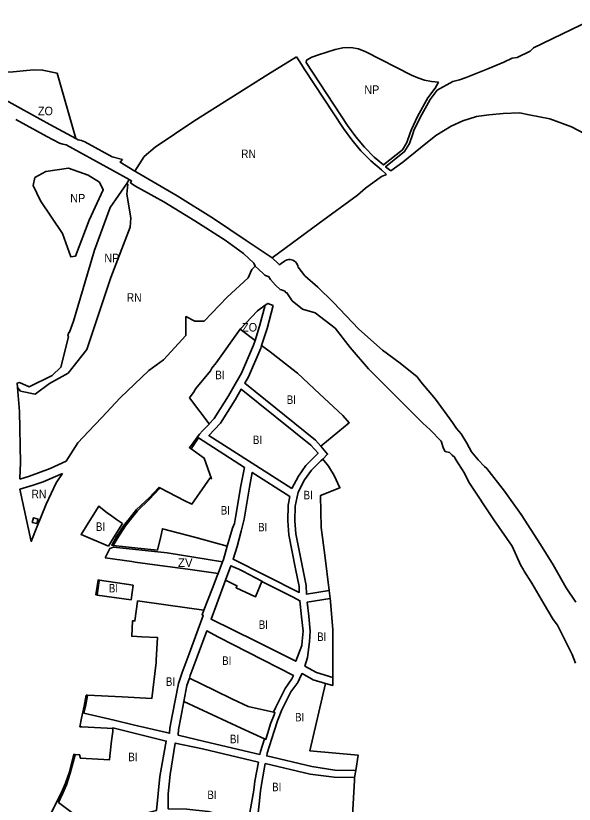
# Model space of a CAD drawing. Extents: x -650971 to -642489, y -1074311 to -1062745.
# Drawn here: x -645941 to -645155, y -1069933 to -1068825 of the extents above; entities that cross this region are included whole.
import ezdxf

# ---------------------------------------------------------------- set-up
doc = ezdxf.new("R2010")
doc.units = 0
doc.header["$LTSCALE"] = 4.8
for name, color, linetype, lineweight in [('15', 7, 'Continuous', 35), ('2', 7, 'Continuous', 35), ('24', 7, 'Continuous', 35), ('40', 7, 'Continuous', 35), ('42', 7, 'Continuous', 35), ('48', 7, 'Continuous', 35), ('62', 7, 'Continuous', 35), ('7', 7, 'Continuous', 35)]:
    doc.layers.add(name, color=color, linetype=linetype, lineweight=lineweight)

msp = doc.modelspace()

# ---------------------------------------------------------------- linework, layer by layer
at = {"layer": '15'}
for points in [[(-645604.114, -1069281.49), (-645597.738, -1069261.522), (-645589.844, -1069231.908), (-645586.39, -1069229.32), (-645578.713, -1069232.375)], [(-645578.713, -1069232.375), (-645587.298, -1069264.578), (-645594.94, -1069288.511)], [(-645668.722, -1069398.75), (-645661.477, -1069390.91), (-645641.511, -1069359.099), (-645635.995, -1069349.527), (-645623.307, -1069327.508), (-645606.256, -1069288.199), (-645604.114, -1069281.49)], [(-645594.94, -1069288.511), (-645596.062, -1069292.027), (-645613.576, -1069332.402), (-645618.766, -1069341.409), (-645519.097, -1069421.579), (-645511.464, -1069429.794)], [(-645678.06, -1069408.54), (-645668.61, -1069398.9), (-645668.722, -1069398.75)], [(-645694.21, -1069433.78), (-645696.45, -1069432.21), (-645682.28, -1069412.88), (-645678.06, -1069408.54)], [(-645643.16, -1069570.6), (-645636.09, -1069545.31), (-645633.29, -1069538.7), (-645631.62, -1069530.161), (-645624.041, -1069485.561), (-645619.119, -1069459.68), (-645683.883, -1069418.357), (-645694.21, -1069433.78)], [(-645511.464, -1069429.794), (-645502.142, -1069441.313), (-645508.994, -1069447.955)], [(-645508.994, -1069447.955), (-645511.585, -1069450.466), (-645524.812, -1069463.425), (-645534.584, -1069477.365), (-645543.548, -1069494.404), (-645547.654, -1069514.049), (-645548.207, -1069534.609), (-645546.74, -1069552.954), (-645537.354, -1069600.095), (-645532.36, -1069625.648), (-645531.753, -1069637.96), (-645500.137, -1069632.833), (-645498.61, -1069643.729)], [(-645803.513, -1069569.263), (-645805.66, -1069569.03), (-645798.53, -1069556.3), (-645787.64, -1069539.88), (-645780.85, -1069531.55), (-645770.66, -1069519.07), (-645753.05, -1069502.47), (-645739.3, -1069487.81), (-645737.897, -1069488.534)], [(-645737.897, -1069488.534), (-645738.986, -1069489.868), (-645752.715, -1069504.328), (-645769.369, -1069520.672), (-645779.376, -1069532.962), (-645786.388, -1069541.673), (-645798.102, -1069559.972), (-645803.513, -1069569.263)], [(-645648.68, -1069589.06), (-645644.56, -1069575.61), (-645643.16, -1069570.6)], [(-645664.19, -1069629.24), (-645657.52, -1069612.2), (-645656.15, -1069608.71), (-645649.91, -1069592.39), (-645648.68, -1069589.06)], [(-645594.818, -1069620.139), (-645594.58, -1069619.56), (-645621.56, -1069605.68), (-645626.95, -1069602.91), (-645638.203, -1069597.8), (-645645.715, -1069618.085)], [(-645827.94, -1069638.8), (-645824.95, -1069618.01), (-645823.082, -1069618.279)], [(-645823.082, -1069618.279), (-645823.13, -1069618.452), (-645825.295, -1069632.053), (-645826.133, -1069638.843), (-645826.15, -1069639.045), (-645827.94, -1069638.8)], [(-645645.715, -1069618.085), (-645658.119, -1069651.601), (-645665.961, -1069673.028), (-645602.91, -1069703.88), (-645546.93, -1069731.98), (-645538.579, -1069710.102), (-645537.8, -1069703.696), (-645536.707, -1069689.842), (-645538.744, -1069669.644), (-645541.064, -1069647.092), (-645550.62, -1069642.176), (-645594.818, -1069620.139)], [(-645839.658, -1069779.835), (-645839.721, -1069780.247), (-645842.728, -1069795.578), (-645844.737, -1069804.875), (-645802.431, -1069814.987), (-645775.326, -1069821.576), (-645724.25, -1069833.353), (-645723.777, -1069826.243), (-645720.632, -1069808.792), (-645711.852, -1069763.14), (-645706.663, -1069747.998), (-645696.794, -1069721.756), (-645676.984, -1069667.634), (-645678.73, -1069666.78), (-645676.34, -1069660.28), (-645670.23, -1069644.67), (-645664.19, -1069629.24)], [(-645498.61, -1069643.729), (-645530.797, -1069648.949), (-645528.772, -1069668.628), (-645526.643, -1069689.732), (-645527.824, -1069704.697), (-645530.534, -1069726.969), (-645533.953, -1069739.166), (-645518, -1069748), (-645495, -1069754.815)], [(-645578.134, -1069803.731), (-645575.153, -1069796.472), (-645561.956, -1069770.224), (-645552.437, -1069756.749), (-645550.184, -1069752.242), (-645614.28, -1069719.27), (-645655.45, -1069698.05), (-645671.999, -1069689.523), (-645685.351, -1069726.002), (-645695.176, -1069752.125), (-645696.517, -1069756.039)], [(-645696.517, -1069756.039), (-645700.028, -1069766.286), (-645704.355, -1069788.786)], [(-645504.976, -1069763.332), (-645522.277, -1069758.205), (-645538.096, -1069749.446), (-645539.126, -1069751.764), (-645544.108, -1069761.733), (-645553.635, -1069775.217), (-645566.341, -1069800.49), (-645572.56, -1069815.628), (-645577.497, -1069830.237), (-645587.052, -1069861.272), (-645587.785, -1069865.117), (-645524.43, -1069879.921), (-645492, -1069885), (-645462.303, -1069885.376), (-645464.288, -1069895.362)], [(-645495, -1069754.815), (-645495, -1069766), (-645504.976, -1069763.332)], [(-645850.63, -1069824.09), (-645848.35, -1069812.09), (-645844.57, -1069795.07), (-645841.41, -1069779.76), (-645839.658, -1069779.835)], [(-645704.355, -1069788.786), (-645708.633, -1069811.027), (-645711.644, -1069827.736), (-645712.203, -1069836.131), (-645675.369, -1069844.625), (-645597.216, -1069862.91), (-645596.458, -1069858.935), (-645590.964, -1069841.09)], [(-645590.964, -1069841.09), (-645589.23, -1069841.89), (-645582.31, -1069820.05), (-645577.52, -1069807.26), (-645576.34, -1069804.13), (-645578.134, -1069803.731)], [(-645857.204, -1069862.954), (-645857.289, -1069863.338), (-645863.95, -1069889.468), (-645869.262, -1069905.935), (-645874.219, -1069917.496), (-645880.431, -1069930.3), (-645833, -1069966), (-645806, -1069959), (-645768.424, -1069948.431), (-645742.967, -1069941.862), (-645738.039, -1069894.231), (-645729.006, -1069844.136), (-645777.852, -1069832.241), (-645804.185, -1069825.84), (-645804.28, -1069826.76)], [(-645804.28, -1069826.76), (-645812.18, -1069826.3), (-645847.62, -1069824.26), (-645850.63, -1069824.09)], [(-645894.25, -1069958.7), (-645895.66, -1069958.42), (-645892.09, -1069947.98), (-645876.15, -1069916.47), (-645870.89, -1069903.5), (-645865.78, -1069888.76), (-645858.78, -1069862.84), (-645857.204, -1069862.954)], [(-645464.288, -1069895.362), (-645492.842, -1069895), (-645526.451, -1069890.745), (-645589.84, -1069875.892), (-645594.866, -1069902.242), (-645596.463, -1069914.335), (-645598.491, -1069932.472), (-645601.753, -1069962.317), (-645547.4, -1069976.382), (-645490.814, -1069988.074), (-645469.701, -1069990.011)]]:
    msp.add_lwpolyline(points, dxfattribs=at)
for points in [[(-645552.336, -1069489.579), (-645543.158, -1069472.134), (-645532.534, -1069456.978), (-645515.509, -1069439.769), (-645525.761, -1069428.736), (-645623.694, -1069349.962), (-645632.191, -1069364.707), (-645652.804, -1069397.548), (-645669.039, -1069415.116)], [(-645555.072, -1069500.545), (-645608.04, -1069466.749), (-645612.028, -1069487.724), (-645619.662, -1069532.642), (-645623.814, -1069549.548), (-645629.102, -1069570.857), (-645635.153, -1069588.78), (-645541.922, -1069635.264), (-645542.336, -1069626.862), (-645547.188, -1069602.035), (-645556.685, -1069554.337), (-645558.241, -1069534.874), (-645557.65, -1069512.879)], [(-645599.271, -1069873.685), (-645677.849, -1069855.3), (-645716.277, -1069847.01), (-645723.668, -1069891.356), (-645726.131, -1069918.457), (-645726.542, -1069939.398), (-645699.889, -1069939.714), (-645670.325, -1069943.002), (-645625.979, -1069954.92), (-645614.072, -1069957.797), (-645606.07, -1069913.163), (-645604.424, -1069900.701)]]:
    msp.add_lwpolyline(points, close=True, dxfattribs=at)
at = {"layer": '2'}
for points in [[(-645696.19, -1069362.01), (-645692.38, -1069356.67), (-645690.81, -1069354.28), (-645687.22, -1069349), (-645667, -1069324.06), (-645664.89, -1069320.2), (-645658.9, -1069312.83), (-645625.11, -1069265.42), (-645604.114, -1069281.49)], [(-645604.114, -1069281.49), (-645606.256, -1069288.199), (-645623.307, -1069327.508), (-645635.995, -1069349.527), (-645641.511, -1069359.099), (-645661.477, -1069390.91), (-645668.722, -1069398.75), (-645696.19, -1069362.01)], [(-645511.464, -1069429.794), (-645519.097, -1069421.579), (-645618.766, -1069341.409), (-645613.576, -1069332.402), (-645596.062, -1069292.027), (-645594.94, -1069288.511)], [(-645594.94, -1069288.511), (-645583.13, -1069297.55), (-645546.19, -1069325.81), (-645544.26, -1069327.35), (-645513.41, -1069356.18), (-645480.72, -1069386.96), (-645471.738, -1069397.026), (-645511.464, -1069429.794)], [(-645694.21, -1069433.78), (-645683.883, -1069418.357), (-645619.119, -1069459.68), (-645624.041, -1069485.561), (-645631.62, -1069530.161), (-645633.29, -1069538.7), (-645636.09, -1069545.31), (-645643.16, -1069570.6)], [(-645737.897, -1069488.534), (-645702.82, -1069506.64), (-645692.87, -1069511.229), (-645667.31, -1069474.6), (-645665.58, -1069475.61), (-645675.91, -1069446.56), (-645694.21, -1069433.78)], [(-645500.137, -1069632.833), (-645531.753, -1069637.96), (-645532.36, -1069625.648), (-645537.354, -1069600.095), (-645546.74, -1069552.954), (-645548.207, -1069534.609), (-645547.654, -1069514.049), (-645543.548, -1069494.404), (-645534.584, -1069477.365), (-645524.812, -1069463.425), (-645511.585, -1069450.466), (-645508.994, -1069447.955)], [(-645508.994, -1069447.955), (-645501, -1069458), (-645493, -1069471), (-645484.783, -1069488.256), (-645512, -1069499), (-645511, -1069544), (-645506, -1069583), (-645500.137, -1069632.833)], [(-645803.513, -1069569.263), (-645798.102, -1069559.972), (-645786.388, -1069541.673), (-645779.376, -1069532.962), (-645769.369, -1069520.672), (-645752.715, -1069504.328), (-645738.986, -1069489.868), (-645737.897, -1069488.534)], [(-645810.08, -1069570.39), (-645848.78, -1069553.91), (-645836.44, -1069534.5), (-645824.05, -1069514.34), (-645811.75, -1069523.81)], [(-645811.75, -1069523.81), (-645808.1, -1069526.61), (-645799.07, -1069532.8), (-645790.62, -1069538.59)], [(-645790.62, -1069538.59), (-645803.07, -1069558.62), (-645810.08, -1069570.39)], [(-645643.16, -1069570.6), (-645687.29, -1069558.04), (-645734.5, -1069545.89), (-645736.8, -1069556.91), (-645741.14, -1069576.19)], [(-645741.14, -1069576.19), (-645769.04, -1069573), (-645803.513, -1069569.263)], [(-645826.15, -1069639.045), (-645826.133, -1069638.843), (-645825.295, -1069632.053), (-645823.13, -1069618.452), (-645823.082, -1069618.279), (-645775.46, -1069625.13)], [(-645594.818, -1069620.139), (-645550.62, -1069642.176), (-645541.064, -1069647.092), (-645538.744, -1069669.644), (-645536.707, -1069689.842), (-645537.8, -1069703.696), (-645538.579, -1069710.102), (-645546.93, -1069731.98), (-645602.91, -1069703.88), (-645665.961, -1069673.028), (-645658.119, -1069651.601), (-645645.715, -1069618.085)], [(-645645.715, -1069618.085), (-645629.78, -1069626.03), (-645630.93, -1069628.84), (-645603.7, -1069641.75), (-645594.818, -1069620.139)], [(-645775.46, -1069625.13), (-645778.45, -1069645.92), (-645826.151, -1069639.057), (-645826.15, -1069639.045)], [(-645495, -1069754.815), (-645518, -1069748), (-645533.953, -1069739.166), (-645530.534, -1069726.969), (-645527.824, -1069704.697), (-645526.643, -1069689.732), (-645528.772, -1069668.628), (-645530.797, -1069648.949), (-645498.61, -1069643.729)], [(-645498.61, -1069643.729), (-645498, -1069648), (-645495, -1069688), (-645495, -1069754.815)], [(-645839.658, -1069779.835), (-645791.2, -1069781.92), (-645749.48, -1069784.61), (-645743.36, -1069733.7), (-645743.01, -1069730.72), (-645741.43, -1069698.68), (-645763.24, -1069697.58), (-645777.62, -1069696.85), (-645776.45, -1069675.26), (-645773.02, -1069675.47), (-645769.36, -1069648), (-645769.264, -1069647.213), (-645726.57, -1069653.22), (-645676.34, -1069660.28)], [(-645676.34, -1069660.28), (-645678.73, -1069666.78), (-645676.984, -1069667.634), (-645696.794, -1069721.756), (-645706.663, -1069747.998), (-645711.852, -1069763.14), (-645720.632, -1069808.792), (-645723.777, -1069826.243), (-645724.25, -1069833.353), (-645775.326, -1069821.576), (-645802.431, -1069814.987), (-645844.737, -1069804.875), (-645842.728, -1069795.578), (-645839.721, -1069780.247), (-645839.658, -1069779.835)], [(-645696.517, -1069756.039), (-645695.176, -1069752.125), (-645685.351, -1069726.002), (-645671.999, -1069689.523), (-645655.45, -1069698.05), (-645614.28, -1069719.27), (-645550.184, -1069752.242), (-645552.437, -1069756.749), (-645561.956, -1069770.224), (-645575.153, -1069796.472), (-645578.134, -1069803.731)], [(-645578.134, -1069803.731), (-645613.84, -1069795.78), (-645635.79, -1069785.23), (-645660.57, -1069773.31), (-645696.517, -1069756.039)], [(-645462.303, -1069885.376), (-645492, -1069885), (-645524.43, -1069879.921), (-645587.785, -1069865.117), (-645587.052, -1069861.272), (-645577.497, -1069830.237), (-645572.56, -1069815.628), (-645566.341, -1069800.49), (-645553.635, -1069775.217), (-645544.108, -1069761.733), (-645539.126, -1069751.764), (-645538.096, -1069749.446), (-645522.277, -1069758.205), (-645504.976, -1069763.332)], [(-645504.976, -1069763.332), (-645527, -1069858), (-645459.312, -1069864.01), (-645462.303, -1069885.376)], [(-645590.964, -1069841.09), (-645596.458, -1069858.935), (-645597.216, -1069862.91), (-645675.369, -1069844.625), (-645712.203, -1069836.131), (-645711.644, -1069827.736), (-645708.633, -1069811.027), (-645704.355, -1069788.786)], [(-645704.355, -1069788.786), (-645623.75, -1069825.97), (-645590.964, -1069841.09)], [(-645804.28, -1069826.76), (-645804.185, -1069825.84), (-645777.852, -1069832.241), (-645729.006, -1069844.136), (-645738.039, -1069894.231), (-645742.967, -1069941.862), (-645768.424, -1069948.431), (-645806, -1069959), (-645833, -1069966), (-645880.431, -1069930.3), (-645874.219, -1069917.496), (-645869.262, -1069905.935), (-645863.95, -1069889.468), (-645857.289, -1069863.338), (-645857.204, -1069862.954)], [(-645857.204, -1069862.954), (-645850.92, -1069863.41), (-645849.79, -1069868.4), (-645808.84, -1069870.75), (-645808.28, -1069865.39), (-645806.07, -1069844.09), (-645804.38, -1069830.61), (-645804.28, -1069826.76)], [(-645469.701, -1069990.011), (-645490.814, -1069988.074), (-645547.4, -1069976.382), (-645601.753, -1069962.317), (-645598.491, -1069932.472), (-645596.463, -1069914.335), (-645594.866, -1069902.242), (-645589.84, -1069875.892), (-645526.451, -1069890.745), (-645492.842, -1069895), (-645464.288, -1069895.362)], [(-645464.288, -1069895.362), (-645464.206, -1069899.449), (-645469.701, -1069990.011)]]:
    msp.add_lwpolyline(points, dxfattribs=at)
for points in [[(-645552.336, -1069489.579), (-645669.039, -1069415.116), (-645652.804, -1069397.548), (-645632.191, -1069364.707), (-645623.694, -1069349.962), (-645525.761, -1069428.736), (-645515.509, -1069439.769), (-645532.534, -1069456.978), (-645543.158, -1069472.134)], [(-645555.072, -1069500.545), (-645557.65, -1069512.879), (-645558.241, -1069534.874), (-645556.685, -1069554.337), (-645547.188, -1069602.035), (-645542.336, -1069626.862), (-645541.922, -1069635.264), (-645635.153, -1069588.78), (-645629.102, -1069570.857), (-645623.814, -1069549.548), (-645619.662, -1069532.642), (-645612.028, -1069487.724), (-645608.04, -1069466.749)], [(-645599.271, -1069873.685), (-645604.424, -1069900.701), (-645606.07, -1069913.163), (-645614.072, -1069957.797), (-645625.979, -1069954.92), (-645670.325, -1069943.002), (-645699.889, -1069939.714), (-645726.542, -1069939.398), (-645726.131, -1069918.457), (-645723.668, -1069891.356), (-645716.277, -1069847.01), (-645677.849, -1069855.3)]]:
    msp.add_lwpolyline(points, close=True, dxfattribs=at)
at = {"layer": '24'}
for points in [[(-646017.55, -1068909.75), (-645975.31, -1068932.8), (-645933.28, -1068955.74), (-645892.77, -1068977.86), (-645856.26, -1068997.79)], [(-645850.79, -1069016.84), (-645869.83, -1069006.45), (-645874.49, -1069005.73), (-645879.17, -1069004.02), (-645896.91, -1068994.75), (-645940.77, -1068970.74)], [(-645856.26, -1068997.79), (-645852.91, -1068999.62), (-645848.18, -1069000.48), (-645843.56, -1069002.41), (-645805.16, -1069023.52), (-645790.53, -1069027.19)], [(-645603.91, -1069176.86), (-645606.11, -1069172.98), (-645620.2, -1069159.26), (-645646.08, -1069140.37), (-645688.87, -1069113.44), (-645732.65, -1069086.82), (-645773.29, -1069063.99), (-645779.49, -1069059.92), (-645777.73, -1069057.2), (-645781.12, -1069055.29), (-645803.29, -1069042.92), (-645850.79, -1069016.84)], [(-645790.53, -1069027.19), (-645793.638, -1069031.021), (-645773.38, -1069043.46)], [(-645773.38, -1069043.46), (-645770.04, -1069045.34), (-645713.61, -1069078.06), (-645662.44, -1069109.89), (-645616.63, -1069140.8), (-645579.94, -1069165.52), (-645571.9, -1069173.43)], [(-645571.9, -1069173.43), (-645569.81, -1069175.03), (-645567.5, -1069173.46), (-645562.95, -1069170.06), (-645561.21, -1069169.02), (-645559.15, -1069168.24), (-645557.15, -1069167.85), (-645554.96, -1069167.8), (-645552.94, -1069168.1), (-645550.86, -1069168.77), (-645548.79, -1069169.88), (-645547.32, -1069171.06), (-645545.78, -1069172.76), (-645544.75, -1069174.39), (-645543.86, -1069176.51), (-645543.43, -1069178.39)], [(-645592.24, -1069187.73), (-645599, -1069181.48), (-645603.91, -1069176.86)], [(-645543.43, -1069178.39), (-645534.25, -1069190.56), (-645515.89, -1069206.66), (-645494.13, -1069227.63), (-645458.45, -1069265.56), (-645424.8, -1069295.24), (-645400.07, -1069313.32), (-645376.38, -1069332.65), (-645371.12, -1069339.47), (-645350.63, -1069363.98), (-645326.59, -1069396.64), (-645321.1, -1069405.21), (-645314.14, -1069412.54), (-645306.16, -1069425.55), (-645299.61, -1069437.97), (-645290.5, -1069449.03), (-645281.4, -1069458.4), (-645278.31, -1069461.33), (-645253.4, -1069493.06), (-645230.1, -1069525.98), (-645202.56, -1069568.23), (-645184.88, -1069596.58), (-645166.67, -1069629), (-645153.33, -1069649.24)], [(-645567.069, -1069210.45), (-645568.9, -1069209.87), (-645575.58, -1069203.57), (-645582.63, -1069195.88), (-645584.73, -1069191.88), (-645590.41, -1069189.45), (-645592.24, -1069187.73)], [(-645153.44, -1069734.71), (-645158.43, -1069722.61), (-645179.12, -1069681.3), (-645185.17, -1069673.38), (-645198.41, -1069650.49), (-645214.76, -1069622.37), (-645225.7, -1069605.32), (-645227.27, -1069602.68), (-645230.42, -1069597.39), (-645242.75, -1069570.26), (-645268.57, -1069533.23), (-645303.57, -1069480.49), (-645309.62, -1069467.79), (-645322.13, -1069447.96), (-645323.36, -1069445.79), (-645327.2, -1069442.53), (-645330.57, -1069438.89), (-645336.66, -1069437.47), (-645339.31, -1069433.27), (-645342.49, -1069423.06), (-645358.04, -1069406.84), (-645368.13, -1069397.37), (-645405.7, -1069360.27), (-645444.62, -1069321.35), (-645470.44, -1069291.24), (-645491.63, -1069264.25), (-645519.59, -1069242.38), (-645537.44, -1069237.41), (-645552.2, -1069225.59), (-645559.33, -1069214.54), (-645560.72, -1069214.25), (-645562.17, -1069212.02), (-645567.069, -1069210.45)]]:
    msp.add_lwpolyline(points, dxfattribs=at)
at = {"layer": '40'}
for points in [[(-645814.82, -1069586.81), (-645808.18, -1069573.7), (-645803.33, -1069571.62), (-645727.71, -1069579.61), (-645649.91, -1069592.39), (-645656.15, -1069608.71)], [(-645656.15, -1069608.71), (-645698.83, -1069602.85), (-645738.13, -1069597.46), (-645772.58, -1069592.73), (-645777.26, -1069592.07), (-645814.82, -1069586.81)]]:
    msp.add_lwpolyline(points, dxfattribs=at)
at = {"layer": '42'}
for points in [[(-645973.36, -1068898.93), (-645954.59, -1068904.41), (-645944.23, -1068904.13), (-645930.1, -1068902.47), (-645915.61, -1068901.02), (-645902.91, -1068901.43), (-645882.63, -1068905.88), (-645856.26, -1068997.79)], [(-645856.26, -1068997.79), (-645892.77, -1068977.86), (-645933.28, -1068955.74), (-645975.31, -1068932.8), (-646017.55, -1068909.75)], [(-645625.11, -1069265.42), (-645600.55, -1069239.93), (-645589.844, -1069231.908)], [(-645589.844, -1069231.908), (-645597.738, -1069261.522), (-645604.114, -1069281.49), (-645625.11, -1069265.42)]]:
    msp.add_lwpolyline(points, dxfattribs=at)
at = {"layer": '48'}
for points in [[(-645413.29, -1069042.92), (-645420.586, -1069037.45), (-645393.954, -1069016.138), (-645387.111, -1069004.801), (-645382.274, -1068990.949), (-645380.699, -1068986.445), (-645371.971, -1068968.389), (-645357.996, -1068942.757), (-645348.066, -1068929.794), (-645326.23, -1068917.37), (-645316.51, -1068915.17), (-645307.16, -1068911.97), (-645276.91, -1068899.79), (-645254.58, -1068890.34), (-645242.64, -1068884.8), (-645235.76, -1068883.92), (-645217.45, -1068875.09), (-645212.72, -1068870.49), (-645119.5, -1068825.24)], [(-644952.47, -1069036.35), (-644988.11, -1069042.51), (-645029.47, -1069037.71), (-645059.3, -1069027.45), (-645090.35, -1069010.56), (-645122.25, -1068993.21), (-645131.73, -1068995.69), (-645159.37, -1068981.11), (-645189.84, -1068969.91), (-645218.85, -1068964.3), (-645232.4, -1068961.67), (-645255.21, -1068962.49), (-645275.45, -1068964.38), (-645292.77, -1068966.91), (-645311.99, -1068972.74), (-645328.55, -1068980.37), (-645350.17, -1068993.33), (-645371.56, -1069010.81), (-645396.53, -1069030.88), (-645413.29, -1069042.92)], [(-645938.399, -1069347.452), (-645938.89, -1069341.56), (-645935.33, -1069340.64), (-645921.56, -1069346.6), (-645889.29, -1069330.52), (-645877.15, -1069319.06), (-645866.45, -1069276.32), (-645867.42, -1069274.21), (-645866.02, -1069270.26), (-645864.96, -1069269.78), (-645859.43, -1069254.08), (-645829.96, -1069154.65), (-645807.89, -1069094.51), (-645784.69, -1069060.74)], [(-645784.69, -1069060.74), (-645783.02, -1069061.84), (-645784.52, -1069075.66), (-645778.75, -1069108.98), (-645779.685, -1069122.296), (-645806.806, -1069193.112), (-645840.644, -1069294.052), (-645867.026, -1069327.317), (-645893.291, -1069341.938), (-645913.23, -1069356.892), (-645933.792, -1069352.53), (-645938.399, -1069347.452)]]:
    msp.add_lwpolyline(points, dxfattribs=at)
for points in [[(-645346.11, -1068918.62), (-645350.78, -1068926.76), (-645361.36, -1068940.57), (-645375.53, -1068966.56), (-645384.4, -1068984.91), (-645386.05, -1068989.63), (-645390.75, -1069003.09), (-645397.01, -1069013.46), (-645423.753, -1069034.862), (-645436.6, -1069023.76), (-645450.17, -1069010.02), (-645462.64, -1068995.27), (-645473.98, -1068979.47), (-645532.39, -1068890.9), (-645531.66, -1068887.61), (-645524.13, -1068883.52), (-645515.12, -1068880), (-645491.61, -1068872.47), (-645480.68, -1068870.12), (-645469.68, -1068869.93), (-645458.84, -1068871.88), (-645448.43, -1068875.95), (-645384.33, -1068908.58), (-645375.3, -1068912.58), (-645365.8, -1068915.63), (-645356.04, -1068917.65)], [(-645822.85, -1069058.8), (-645817.59, -1069069.6), (-645837.21, -1069112.54), (-645856.76, -1069163.17), (-645863.38, -1069163.79), (-645874.98, -1069131.01), (-645905.94, -1069085.11), (-645916.2, -1069063.8), (-645913.8, -1069052.51), (-645898.57, -1069044.24), (-645866.69, -1069039.37), (-645838.99, -1069049.31)]]:
    msp.add_lwpolyline(points, close=True, dxfattribs=at)
at = {"layer": '7'}
for points in [[(-645773.38, -1069043.46), (-645760.07, -1069023.11), (-645744.65, -1069009.71), (-645690.34, -1068973.16), (-645586.28, -1068907.71), (-645545.679, -1068882.991)], [(-645545.679, -1068882.991), (-645541.34, -1068889.93), (-645534.94, -1068899.86), (-645479.67, -1068983.55), (-645468.16, -1068999.57), (-645455.35, -1069014.76), (-645441.38, -1069028.88), (-645426.46, -1069041.78), (-645419.17, -1069048.02)], [(-645579.94, -1069165.52), (-645616.63, -1069140.8), (-645662.44, -1069109.89), (-645713.61, -1069078.06), (-645770.04, -1069045.34), (-645773.38, -1069043.46)], [(-645419.17, -1069048.02), (-645426.3, -1069051.02), (-645449.03, -1069067.42), (-645459.91, -1069077.37), (-645514.08, -1069116.5), (-645579.94, -1069165.52)], [(-645938.399, -1069347.452), (-645933.792, -1069352.53), (-645913.23, -1069356.892), (-645893.291, -1069341.938), (-645867.026, -1069327.317), (-645840.644, -1069294.052), (-645806.806, -1069193.112), (-645779.685, -1069122.296), (-645778.75, -1069108.98), (-645784.52, -1069075.66), (-645783.02, -1069061.84), (-645784.69, -1069060.74), (-645781.12, -1069055.29)], [(-645781.12, -1069055.29), (-645777.73, -1069057.2), (-645779.49, -1069059.92), (-645773.29, -1069063.99), (-645732.65, -1069086.82), (-645688.87, -1069113.44), (-645646.08, -1069140.37), (-645620.2, -1069159.26), (-645606.11, -1069172.98), (-645603.91, -1069176.86)], [(-645603.91, -1069176.86), (-645608.71, -1069181.51), (-645613.9, -1069193.45), (-645643.34, -1069220.59), (-645675.823, -1069254.48)], [(-645675.823, -1069254.48), (-645689, -1069254.5), (-645701.33, -1069247.86), (-645701.52, -1069256.86), (-645701.62, -1069274.36), (-645733.1, -1069308.58), (-645753.58, -1069323.64), (-645793.63, -1069362.15), (-645819.62, -1069389.66), (-645838.17, -1069409.28), (-645853.28, -1069425.27), (-645869.91, -1069451.02)], [(-645934.86, -1069476.27), (-645934.8, -1069474.71), (-645933.97, -1069453.52), (-645935.58, -1069381.24), (-645938.399, -1069347.452)], [(-645869.91, -1069451.02), (-645892.03, -1069461.43), (-645921.13, -1069472.25), (-645928.99, -1069474.55), (-645934.86, -1069476.27)], [(-645934.97, -1069490.31), (-645916.13, -1069484.55), (-645902.19, -1069480.13), (-645875.02, -1069468.52)], [(-645875.02, -1069468.52), (-645884.01, -1069481.56), (-645897.92, -1069511.49), (-645910.9, -1069543.64), (-645918.82, -1069563.81), (-645934.97, -1069490.31)]]:
    msp.add_lwpolyline(points, dxfattribs=at)
msp.add_lwpolyline([(-645910.85, -1069538.44), (-645909.19, -1069532.46), (-645915.7, -1069530.41), (-645917.55, -1069537.16)], close=True, dxfattribs=at)

# ---------------------------------------------------------------- texts
at = {"layer": '62'}
for s, width, p in [('NP', 0.95, (-645450.583, -1068935.041)), ('ZO', 0.95, (-645909.476, -1068965.017)), ('RN', 0.9, (-645623.83, -1069025.21)), ('NP', 0.95, (-645864.111, -1069087.517)), ('NP', 0.95, (-645816.111, -1069171.517)), ('RN', 0.9, (-645784.603, -1069226.978)), ('ZO', 0.95, (-645622.428, -1069268.829)), ('BI', 0.85, (-645659.967, -1069335.79)), ('BI', 0.85, (-645559.537, -1069370.602)), ('BI', 0.85, (-645607.166, -1069426.988)), ('RN', 0.9, (-645918.459, -1069503.176)), ('BI', 0.85, (-645535.874, -1069504.638)), ('BI', 0.85, (-645652.376, -1069526.009)), ('BI', 0.85, (-645827.899, -1069548.998)), ('BI', 0.85, (-645599.874, -1069549.638)), ('BI', 0.85, (-645809.789, -1069635.433)), ('BI', 0.85, (-645598.928, -1069686.593)), ('BI', 0.85, (-645516.874, -1069703.638)), ('BI', 0.85, (-645650.447, -1069737.266)), ('BI', 0.85, (-645729.524, -1069766.68)), ('BI', 0.85, (-645547.874, -1069816.638)), ('BI', 0.85, (-645639.447, -1069847.266)), ('BI', 0.85, (-645782.319, -1069872.497)), ('BI', 0.85, (-645580.138, -1069914.734)), ('BI', 0.85, (-645671.138, -1069925.734))]:
    msp.add_text(s, height=12, dxfattribs=dict(at, width=width)).set_placement(p)
msp.add_text('ZV', height=12, dxfattribs=at).set_placement((-645712.51, -1069599.456))

doc.saveas('drawing.dxf')
